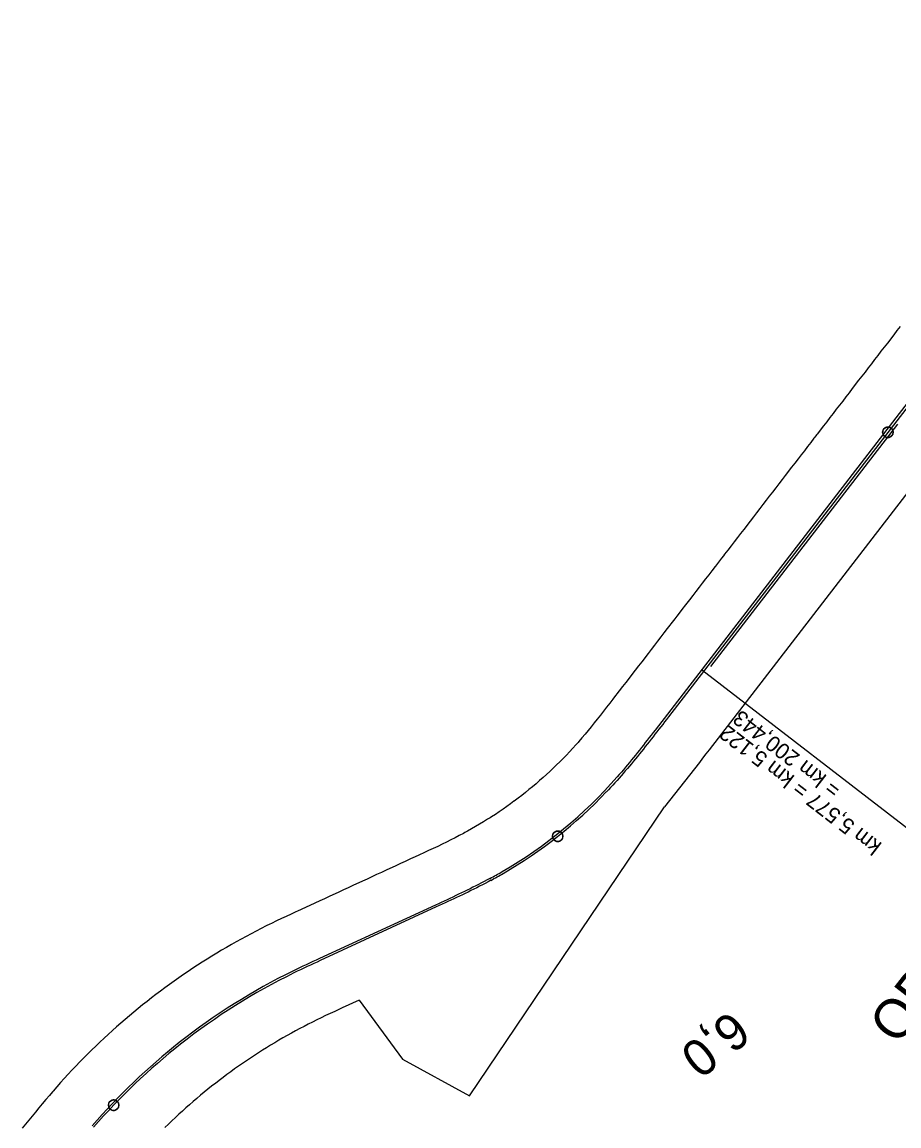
# Model space of a CAD drawing. Extents: x -670810 to -649614, y -1131928 to -1115069.
# Drawn here: x -669557 to -667879, y -1127234 to -1125122 of the extents above; entities that cross this region are included whole.
import ezdxf

# ---------------------------------------------------------------- set-up
doc = ezdxf.new("R2010")
doc.units = 0
for name, color, linetype in [('519 Var SK-4 Praporky stanic', 7, 'Continuous'), ('hranice_VRT_ZUR_Vysocina', 7, 'Continuous'), ('Situace - Osa koleje 2D', 7, 'Continuous'), ('Situace - Osa koleje tunel 2D', 7, 'Continuous'), ('Staničení - hlavní staničení + kolečka 1k', 7, 'Continuous')]:
    doc.layers.add(name, color=color, linetype=linetype)

# ---------------------------------------------------------------- blocks, each defined once
blk = doc.blocks.new('Sit10Kruh_172')
at = {"layer": 'Staničení - hlavní staničení + kolečka 1k'}
blk.add_lwpolyline([(10, 0), (9.98026, 0.6279), (9.92114, 1.25334), (9.82288, 1.87382), (9.68584, 2.4869), (9.51056, 3.09016), (9.29776, 3.68124), (9.04828, 4.2578), (8.76306, 4.81754), (8.44328, 5.35826), (8.09016, 5.87786), (7.70514, 6.37424), (7.28968, 6.84548), (6.84548, 7.28968), (6.37424, 7.70514), (5.87786, 8.09016), (5.35826, 8.44328), (4.81754, 8.76306), (4.2578, 9.04828), (3.68124, 9.29776), (3.09016, 9.51056), (2.4869, 9.68584), (1.87382, 9.82288), (1.25334, 9.92114), (0.6279, 9.98026), (0, 10), (-0.6279, 9.98026), (-1.25334, 9.92114), (-1.87382, 9.82288), (-2.4869, 9.68584), (-3.09016, 9.51056), (-3.68124, 9.29776), (-4.2578, 9.04828), (-4.81754, 8.76306), (-5.35826, 8.44328), (-5.87786, 8.09016), (-6.37424, 7.70514), (-6.84548, 7.28968), (-7.28968, 6.84548), (-7.70514, 6.37424), (-8.09016, 5.87786), (-8.44328, 5.35826), (-8.76306, 4.81754), (-9.04828, 4.2578), (-9.29776, 3.68124), (-9.51056, 3.09016), (-9.68584, 2.4869), (-9.82288, 1.87382), (-9.92114, 1.25334), (-9.98026, 0.6279), (-10, 0), (-9.98026, -0.6279), (-9.92114, -1.25334), (-9.82288, -1.87382), (-9.68584, -2.4869), (-9.51056, -3.09016), (-9.29776, -3.68124), (-9.04828, -4.2578), (-8.76306, -4.81754), (-8.44328, -5.35826), (-8.09016, -5.87786), (-7.70514, -6.37424), (-7.28968, -6.84548), (-6.84548, -7.28968), (-6.37424, -7.70514), (-5.87786, -8.09016), (-5.35826, -8.44328), (-4.81754, -8.76306), (-4.2578, -9.04828), (-3.68124, -9.29776), (-3.09016, -9.51056), (-2.4869, -9.68584), (-1.87382, -9.82288), (-1.25334, -9.92114), (-0.6279, -9.98026), (0, -10), (0.6279, -9.98026), (1.25334, -9.92114), (1.87382, -9.82288), (2.4869, -9.68584), (3.09016, -9.51056), (3.68124, -9.29776), (4.2578, -9.04828), (4.81754, -8.76306), (5.35826, -8.44328), (5.87786, -8.09016), (6.37424, -7.70514), (6.84548, -7.28968), (7.28968, -6.84548), (7.70514, -6.37424), (8.09016, -5.87786), (8.44328, -5.35826), (8.76306, -4.81754), (9.04828, -4.2578), (9.29776, -3.68124), (9.51056, -3.09016), (9.68584, -2.4869), (9.82288, -1.87382), (9.92114, -1.25334)], close=True, dxfattribs=at)
blk.add_circle((0, 0), 10, dxfattribs=at)
blk = doc.blocks.new('Sit10Kruh_173')
at = {"layer": 'Staničení - hlavní staničení + kolečka 1k'}
blk.add_lwpolyline([(10, 0), (10, 0.6), (9.9, 1.3), (9.8, 1.9), (9.7, 2.5), (9.5, 3.1), (9.3, 3.7), (9, 4.3), (8.8, 4.8), (8.4, 5.4), (8.1, 5.9), (7.7, 6.4), (7.3, 6.8), (6.8, 7.3), (6.4, 7.7), (5.9, 8.1), (5.4, 8.4), (4.8, 8.8), (4.3, 9), (3.7, 9.3), (3.1, 9.5), (2.5, 9.7), (1.9, 9.8), (1.3, 9.9), (0.6, 10), (0, 10), (-0.6, 10), (-1.3, 9.9), (-1.9, 9.8), (-2.5, 9.7), (-3.1, 9.5), (-3.7, 9.3), (-4.3, 9), (-4.8, 8.8), (-5.4, 8.4), (-5.9, 8.1), (-6.4, 7.7), (-6.8, 7.3), (-7.3, 6.8), (-7.7, 6.4), (-8.1, 5.9), (-8.4, 5.4), (-8.8, 4.8), (-9, 4.3), (-9.3, 3.7), (-9.5, 3.1), (-9.7, 2.5), (-9.8, 1.9), (-9.9, 1.3), (-10, 0.6), (-10, 0), (-10, -0.6), (-9.9, -1.3), (-9.8, -1.9), (-9.7, -2.5), (-9.5, -3.1), (-9.3, -3.7), (-9, -4.3), (-8.8, -4.8), (-8.4, -5.4), (-8.1, -5.9), (-7.7, -6.4), (-7.3, -6.8), (-6.8, -7.3), (-6.4, -7.7), (-5.9, -8.1), (-5.4, -8.4), (-4.8, -8.8), (-4.3, -9), (-3.7, -9.3), (-3.1, -9.5), (-2.5, -9.7), (-1.9, -9.8), (-1.3, -9.9), (-0.6, -10), (0, -10), (0.6, -10), (1.3, -9.9), (1.9, -9.8), (2.5, -9.7), (3.1, -9.5), (3.7, -9.3), (4.3, -9), (4.8, -8.8), (5.4, -8.4), (5.9, -8.1), (6.4, -7.7), (6.8, -7.3), (7.3, -6.8), (7.7, -6.4), (8.1, -5.9), (8.4, -5.4), (8.8, -4.8), (9, -4.3), (9.3, -3.7), (9.5, -3.1), (9.7, -2.5), (9.8, -1.9), (9.9, -1.3)], close=True, dxfattribs=at)
blk.add_circle((0, 0), 10, dxfattribs=at)
blk = doc.blocks.new('Sit10Kruh_174')
at = {"layer": 'Staničení - hlavní staničení + kolečka 1k'}
blk.add_lwpolyline([(10, 0), (10, 0.6), (9.9, 1.3), (9.8, 1.9), (9.7, 2.5), (9.5, 3.1), (9.3, 3.7), (9, 4.3), (8.8, 4.8), (8.4, 5.4), (8.1, 5.9), (7.7, 6.4), (7.3, 6.8), (6.8, 7.3), (6.4, 7.7), (5.9, 8.1), (5.4, 8.4), (4.8, 8.8), (4.3, 9), (3.7, 9.3), (3.1, 9.5), (2.5, 9.7), (1.9, 9.8), (1.3, 9.9), (0.6, 10), (0, 10), (-0.6, 10), (-1.3, 9.9), (-1.9, 9.8), (-2.5, 9.7), (-3.1, 9.5), (-3.7, 9.3), (-4.3, 9), (-4.8, 8.8), (-5.4, 8.4), (-5.9, 8.1), (-6.4, 7.7), (-6.8, 7.3), (-7.3, 6.8), (-7.7, 6.4), (-8.1, 5.9), (-8.4, 5.4), (-8.8, 4.8), (-9, 4.3), (-9.3, 3.7), (-9.5, 3.1), (-9.7, 2.5), (-9.8, 1.9), (-9.9, 1.3), (-10, 0.6), (-10, 0), (-10, -0.6), (-9.9, -1.3), (-9.8, -1.9), (-9.7, -2.5), (-9.5, -3.1), (-9.3, -3.7), (-9, -4.3), (-8.8, -4.8), (-8.4, -5.4), (-8.1, -5.9), (-7.7, -6.4), (-7.3, -6.8), (-6.8, -7.3), (-6.4, -7.7), (-5.9, -8.1), (-5.4, -8.4), (-4.8, -8.8), (-4.3, -9), (-3.7, -9.3), (-3.1, -9.5), (-2.5, -9.7), (-1.9, -9.8), (-1.3, -9.9), (-0.6, -10), (0, -10), (0.6, -10), (1.3, -9.9), (1.9, -9.8), (2.5, -9.7), (3.1, -9.5), (3.7, -9.3), (4.3, -9), (4.8, -8.8), (5.4, -8.4), (5.9, -8.1), (6.4, -7.7), (6.8, -7.3), (7.3, -6.8), (7.7, -6.4), (8.1, -5.9), (8.4, -5.4), (8.8, -4.8), (9, -4.3), (9.3, -3.7), (9.5, -3.1), (9.7, -2.5), (9.8, -1.9), (9.9, -1.3)], close=True, dxfattribs=at)
blk.add_circle((0, 0), 10, dxfattribs=at)
blk = doc.blocks.new('_U522')
at = {"layer": '519 Var SK-4 Praporky stanic'}
blk.add_line((-411.5, 371.7), (63.5, 5.5), dxfattribs=at)
blk.add_lwpolyline([(63.5, 5.5), (155.1, 124.3), (85, 115.2), (75.9, 185.3), (-15.7, 66.5)], close=True, dxfattribs=at)
for s, height, rotation, p in [('ODB BED∅ICHOV', 75, 52.3677, (-36.1, -349)), ('= km 200,443', 30, 142.3677, (-142.9, 146.9)), ('km 5,577 = km 5,122', 30, 142.3677, (-64.7, 38.4))]:
    blk.add_text(s, height=height, rotation=rotation, dxfattribs=at).set_placement(p)

msp = doc.modelspace()

# ---------------------------------------------------------------- linework, layer by layer
at = {"layer": 'hranice_VRT_ZUR_Vysocina'}
for points in [[(-667168.8, -1125122.3), (-668242.2, -1126514.6), (-668248.3, -1126522.6), (-668254.5, -1126530.6), (-668260.7, -1126538.6), (-668327.2, -1126624)], [(-667876.6, -1125704.7), (-667882.7, -1125712.6), (-667888.8, -1125720.6), (-667901.1, -1125736.4), (-667907.2, -1125744.3), (-667913.3, -1125752.2), (-667919.4, -1125760.2), (-667925.5, -1125768.1), (-667931.6, -1125776), (-667937.7, -1125783.9), (-667943.8, -1125791.8), (-667949.9, -1125799.7), (-667956, -1125807.7), (-667968.2, -1125823.5), (-667974.3, -1125831.4), (-667980.4, -1125839.3), (-667986.5, -1125847.3), (-667992.6, -1125855.2), (-667998.8, -1125863.1), (-668004.9, -1125871), (-668011, -1125878.9), (-668017.1, -1125886.9), (-668023.2, -1125894.8), (-668035.4, -1125910.6), (-668036.7, -1125912.3), (-668039.7, -1125916.2), (-668041.5, -1125918.5), (-668047.6, -1125926.5), (-668053.7, -1125934.4), (-668059.8, -1125942.3), (-668065.9, -1125950.2), (-668072, -1125958.1), (-668078.1, -1125966.1), (-668084.2, -1125974), (-668096.4, -1125989.8), (-668102.6, -1125997.7), (-668108.7, -1126005.7), (-668114.8, -1126013.6), (-668120.9, -1126021.5), (-668127, -1126029.4), (-668133.1, -1126037.3), (-668139.2, -1126045.3), (-668145.3, -1126053.2), (-668151.4, -1126061.1), (-668157.5, -1126069), (-668163.6, -1126076.9), (-668175.8, -1126092.8), (-668181.9, -1126100.7), (-668188, -1126108.6), (-668194.1, -1126116.5), (-668200.2, -1126124.4), (-668206.4, -1126132.4), (-668212.5, -1126140.3), (-668214.7, -1126143.2), (-668218.6, -1126148.2), (-668230, -1126163), (-668230.8, -1126164), (-668236.9, -1126172), (-668243, -1126179.9), (-668249.1, -1126187.8), (-668255.2, -1126195.7), (-668261.3, -1126203.6), (-668267.4, -1126211.6), (-668273.5, -1126219.5), (-668279.6, -1126227.4), (-668289.7, -1126240.5), (-668291.8, -1126243.2), (-668304.1, -1126259.1), (-668308, -1126264.3), (-668310.2, -1126267), (-668322.4, -1126282.8), (-668328.5, -1126290.8), (-668334.6, -1126298.7), (-668340.7, -1126306.6), (-668346.8, -1126314.5), (-668352.9, -1126322.4), (-668359, -1126330.4), (-668371.2, -1126346.2), (-668377.3, -1126354.1), (-668383.4, -1126362), (-668401.7, -1126385.8), (-668407.8, -1126393.7), (-668414, -1126401.6), (-668424.8, -1126415.7), (-668426.2, -1126417.5), (-668432.2, -1126425.3), (-668438.2, -1126433.1), (-668444.2, -1126440.8), (-668450.1, -1126448.4), (-668456.1, -1126455.9), (-668461.9, -1126463.2), (-668467.8, -1126470.5), (-668473.7, -1126477.7), (-668479.5, -1126484.7), (-668485.4, -1126491.6), (-668491.3, -1126498.5), (-668493, -1126500.4), (-668497.1, -1126505), (-668503.1, -1126511.6), (-668509.1, -1126518.2), (-668515.2, -1126524.6), (-668521.4, -1126531), (-668527.6, -1126537.3), (-668533.9, -1126543.5), (-668540.3, -1126549.7), (-668546.8, -1126555.8), (-668553.3, -1126561.8), (-668559.9, -1126567.8), (-668566.5, -1126573.6), (-668573.2, -1126579.5), (-668580, -1126585.2), (-668586.9, -1126590.8), (-668593.8, -1126596.4), (-668600.7, -1126601.9), (-668607.8, -1126607.3), (-668615.1, -1126612.8), (-668615.5, -1126613.1), (-668622, -1126617.9), (-668629.2, -1126623.1), (-668636.5, -1126628.2), (-668643.8, -1126633.2), (-668651.2, -1126638.1), (-668658.8, -1126643), (-668661.3, -1126644.6), (-668666.1, -1126647.6), (-668673.7, -1126652.4), (-668681.3, -1126657), (-668688.9, -1126661.5), (-668696.6, -1126665.9), (-668704.5, -1126670.3), (-668709.3, -1126672.9), (-668712, -1126674.4), (-668720.1, -1126678.7), (-668728.2, -1126682.9), (-668736.3, -1126687), (-668744.6, -1126691.1), (-668753, -1126695.2), (-668761.5, -1126699.3), (-668770.1, -1126703.4), (-668778.9, -1126707.5), (-668787.7, -1126711.6), (-668796.6, -1126715.7), (-668805.6, -1126719.9), (-668807.6, -1126720.8), (-668814.7, -1126724.1), (-668823.8, -1126728.3), (-668832.9, -1126732.4), (-668841.9, -1126736.6), (-668860.1, -1126745), (-668869.2, -1126749.2), (-668878.3, -1126753.4), (-668887.3, -1126757.6), (-668896.4, -1126761.8), (-668905.5, -1126766), (-668923.7, -1126774.3), (-668932.7, -1126778.5), (-668941.8, -1126782.7), (-668950.9, -1126786.9), (-668969.1, -1126795.3), (-668978.1, -1126799.5), (-668987.2, -1126803.7), (-668996.3, -1126807.8), (-669014.5, -1126816.2), (-669029.6, -1126823.2), (-669032.7, -1126824.6), (-669041.8, -1126828.9), (-669051.2, -1126833.2), (-669060.6, -1126837.6), (-669070.1, -1126842.1), (-669079.7, -1126846.7), (-669082.5, -1126848.1), (-669089.5, -1126851.6), (-669099.1, -1126856.4), (-669108.8, -1126861.3), (-669118.4, -1126866.4), (-669127.9, -1126871.5), (-669137.4, -1126876.6), (-669146.9, -1126881.9), (-669156.3, -1126887.2), (-669165.7, -1126892.6), (-669175, -1126898.1), (-669184.3, -1126903.7), (-669193.5, -1126909.3), (-669202.7, -1126915), (-669211.9, -1126920.8), (-669221, -1126926.7), (-669230, -1126932.6), (-669239, -1126938.6), (-669248, -1126944.7), (-669256.9, -1126950.9), (-669265.7, -1126957.1), (-669274.5, -1126963.4), (-669283.3, -1126969.8), (-669292, -1126976.2), (-669300.6, -1126982.7), (-669309.2, -1126989.3), (-669317.7, -1126996), (-669326.2, -1127002.7), (-669334.6, -1127009.5), (-669343, -1127016.4), (-669351.3, -1127023.3), (-669359.5, -1127030.4), (-669367.7, -1127037.4), (-669375.8, -1127044.6), (-669383.9, -1127051.8), (-669391.9, -1127059.1), (-669399.9, -1127066.4), (-669407.8, -1127073.8), (-669415.6, -1127081.3), (-669423.4, -1127088.8), (-669431.1, -1127096.4), (-669438.7, -1127104.1), (-669446.3, -1127111.8), (-669453.8, -1127119.6), (-669461.3, -1127127.4), (-669468.7, -1127135.4), (-669476, -1127143.3), (-669483.2, -1127151.4), (-669490.4, -1127159.4), (-669497.5, -1127167.5), (-669498.7, -1127168.9), (-669504.6, -1127175.8), (-669511.4, -1127183.8), (-669518.2, -1127191.9), (-669524.8, -1127199.8), (-669531.3, -1127207.7), (-669537.7, -1127215.4), (-669544, -1127223.1), (-669550.4, -1127230.9), (-669556.8, -1127238.6)], [(-668911.9, -1126993.6), (-668828.9, -1127106.3), (-668700.4, -1127176.7), (-668327.2, -1126624)], [(-668911.9, -1126993.6), (-668944.2, -1127008.4), (-668949.5, -1127010.9), (-668958.5, -1127015.1), (-668967.3, -1127019.1), (-668975.9, -1127023.2), (-668984.4, -1127027.2), (-668992.7, -1127031.3), (-669000.9, -1127035.4), (-669009.1, -1127039.5), (-669017.3, -1127043.7), (-669025.4, -1127048), (-669033.5, -1127052.3), (-669041.5, -1127056.7), (-669049.5, -1127061.2), (-669057.5, -1127065.7), (-669065.4, -1127070.3), (-669073.3, -1127075), (-669081.2, -1127079.7), (-669089, -1127084.5), (-669096.8, -1127089.4), (-669104.5, -1127094.3), (-669112.2, -1127099.3), (-669119.9, -1127104.3), (-669127.5, -1127109.5), (-669135.1, -1127114.6), (-669142.6, -1127119.9), (-669150.1, -1127125.2), (-669157.5, -1127130.6), (-669164.9, -1127136), (-669172.3, -1127141.5), (-669179.6, -1127147), (-669186.9, -1127152.7), (-669191.6, -1127156.3), (-669194, -1127158.2), (-669201.2, -1127164), (-669208.3, -1127169.8), (-669215.4, -1127175.6), (-669222.4, -1127181.6), (-669229.4, -1127187.5), (-669236.3, -1127193.5), (-669243.2, -1127199.6), (-669250, -1127205.7), (-669256.8, -1127211.9), (-669263.5, -1127218.2), (-669270.2, -1127224.5), (-669276.8, -1127230.8), (-669283.4, -1127237.2)]]:
    msp.add_lwpolyline(points, dxfattribs=at)
at = {"layer": 'Situace - Osa koleje 2D'}
for p, q in [((-667817.8, -1125792.2), (-668345.6, -1126476.7)), ((-667813.2, -1125794.4), (-668319.9, -1126451.6)), ((-667882, -1125891.8), (-668239.5, -1126355.5))]:
    msp.add_line(p, q, dxfattribs=at)
for points in [[(-668319.9, -1126451.6), (-668323.6, -1126456.3), (-668327.2, -1126461.1), (-668330.9, -1126465.9), (-668334.6, -1126470.6), (-668338.3, -1126475.4), (-668342, -1126480.1), (-668345.7, -1126484.9), (-668349.4, -1126489.6), (-668353.1, -1126494.4), (-668356.8, -1126499.1), (-668360.5, -1126503.8), (-668364.3, -1126508.5), (-668368, -1126513.3), (-668371.8, -1126517.9), (-668375.6, -1126522.6), (-668379.4, -1126527.3), (-668383.2, -1126532), (-668387, -1126536.6), (-668390.9, -1126541.2), (-668394.8, -1126545.8), (-668398.6, -1126550.4), (-668402.6, -1126555), (-668406.5, -1126559.6), (-668410.4, -1126564.1), (-668414.4, -1126568.6), (-668418.4, -1126573.1), (-668422.5, -1126577.6), (-668426.5, -1126582), (-668430.6, -1126586.5), (-668434.7, -1126590.9), (-668438.8, -1126595.2)], [(-668345.6, -1126476.7), (-668349.3, -1126481.5), (-668353, -1126486.3), (-668356.7, -1126491.1), (-668360.4, -1126495.9), (-668364.2, -1126500.7), (-668367.9, -1126505.5), (-668371.6, -1126510.3), (-668375.4, -1126515.1), (-668379.2, -1126519.8), (-668382.9, -1126524.6), (-668386.7, -1126529.3), (-668390.6, -1126534), (-668394.4, -1126538.7), (-668398.3, -1126543.4), (-668402.1, -1126548.1), (-668406.1, -1126552.7), (-668410, -1126557.3), (-668414, -1126561.9), (-668417.9, -1126566.5)]]:
    msp.add_lwpolyline(points, dxfattribs=at)
for centre, radius, start, end in [((-669086.1, -1125978.6), 890, 300.2232, 318.6555), ((-669086.1, -1125978.6), 894, 300.2145, 316.3875), ((-668504.6, -1128028.2), 1214, 128.2319, 139.1501), ((-668504.6, -1128028.2), 1210, 128.2319, 139.1479)]:
    msp.add_arc(centre, radius, start, end, dxfattribs=at)
at = {"layer": 'Situace - Osa koleje tunel 2D'}
for p, q in [((-668765.7, -1126811.6), (-668987.7, -1126914)), ((-668764.2, -1126815.3), (-668986.1, -1126917.6))]:
    msp.add_line(p, q, dxfattribs=at)
for points in [[(-668661.5, -1126760.8), (-668666.9, -1126763.6), (-668672.3, -1126766.5), (-668677.7, -1126769.3), (-668683.1, -1126772.1), (-668688.5, -1126774.9), (-668694, -1126777.6), (-668699.5, -1126780.3), (-668705, -1126783), (-668710.4, -1126785.7), (-668715.9, -1126788.3), (-668721.5, -1126791), (-668727, -1126793.6), (-668732.5, -1126796.2), (-668738, -1126798.8), (-668743.6, -1126801.4), (-668749.1, -1126803.9), (-668754.6, -1126806.5), (-668760.2, -1126809), (-668765.7, -1126811.6)], [(-668659.7, -1126764.3), (-668665.1, -1126767.2), (-668670.5, -1126770.1), (-668675.9, -1126772.9), (-668681.4, -1126775.7), (-668686.8, -1126778.5), (-668692.3, -1126781.2), (-668697.8, -1126784), (-668703.3, -1126786.7), (-668708.8, -1126789.3), (-668714.3, -1126792), (-668719.8, -1126794.6), (-668725.3, -1126797.2), (-668730.9, -1126799.8), (-668736.4, -1126802.4), (-668742, -1126805), (-668747.5, -1126807.6), (-668753.1, -1126810.2), (-668758.6, -1126812.7), (-668764.2, -1126815.3)], [(-668987.7, -1126914), (-668994.1, -1126916.9), (-669000.4, -1126919.9), (-669006.8, -1126922.8), (-669013.1, -1126925.8), (-669019.5, -1126928.8), (-669025.8, -1126931.8), (-669032.1, -1126934.8), (-669038.4, -1126937.9)], [(-668986.1, -1126917.6), (-668992.4, -1126920.6), (-668998.8, -1126923.5), (-669005.1, -1126926.5), (-669011.5, -1126929.4), (-669017.8, -1126932.4), (-669024.1, -1126935.4), (-669030.4, -1126938.4), (-669036.7, -1126941.5)]]:
    msp.add_lwpolyline(points, dxfattribs=at)
for centre, radius, start, end in [((-669086.1, -1125978.6), 890, 298.4965, 300.2232), ((-669086.1, -1125978.6), 894, 298.4881, 300.2145), ((-668504.6, -1128028.2), 1214, 116.0863, 128.2319), ((-668504.6, -1128028.2), 1210, 116.0884, 128.2319)]:
    msp.add_arc(centre, radius, start, end, dxfattribs=at)

# ---------------------------------------------------------------- block references
at = {"layer": '519 Var SK-4 Praporky stanic'}
msp.add_blockref('_U522', (-667845, -1126732.9), dxfattribs=at)
at = {"layer": 'Staničení - hlavní staničení + kolečka 1k'}
for name, p, rotation in [('Sit10Kruh_172', (-667900.1, -1125907.1), -127.63230700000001), ('Sit10Kruh_173', (-668531.8, -1126680), -141.67919700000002), ('Sit10Kruh_174', (-669381.6, -1127194.5), -133.552264)]:
    msp.add_blockref(name, p, dxfattribs=dict(at, rotation=rotation))

# ---------------------------------------------------------------- texts
msp.add_text('6,0', height=70, rotation=218.3208, dxfattribs=at).set_placement((-668200.3, -1127010.7))

doc.saveas('drawing.dxf')
